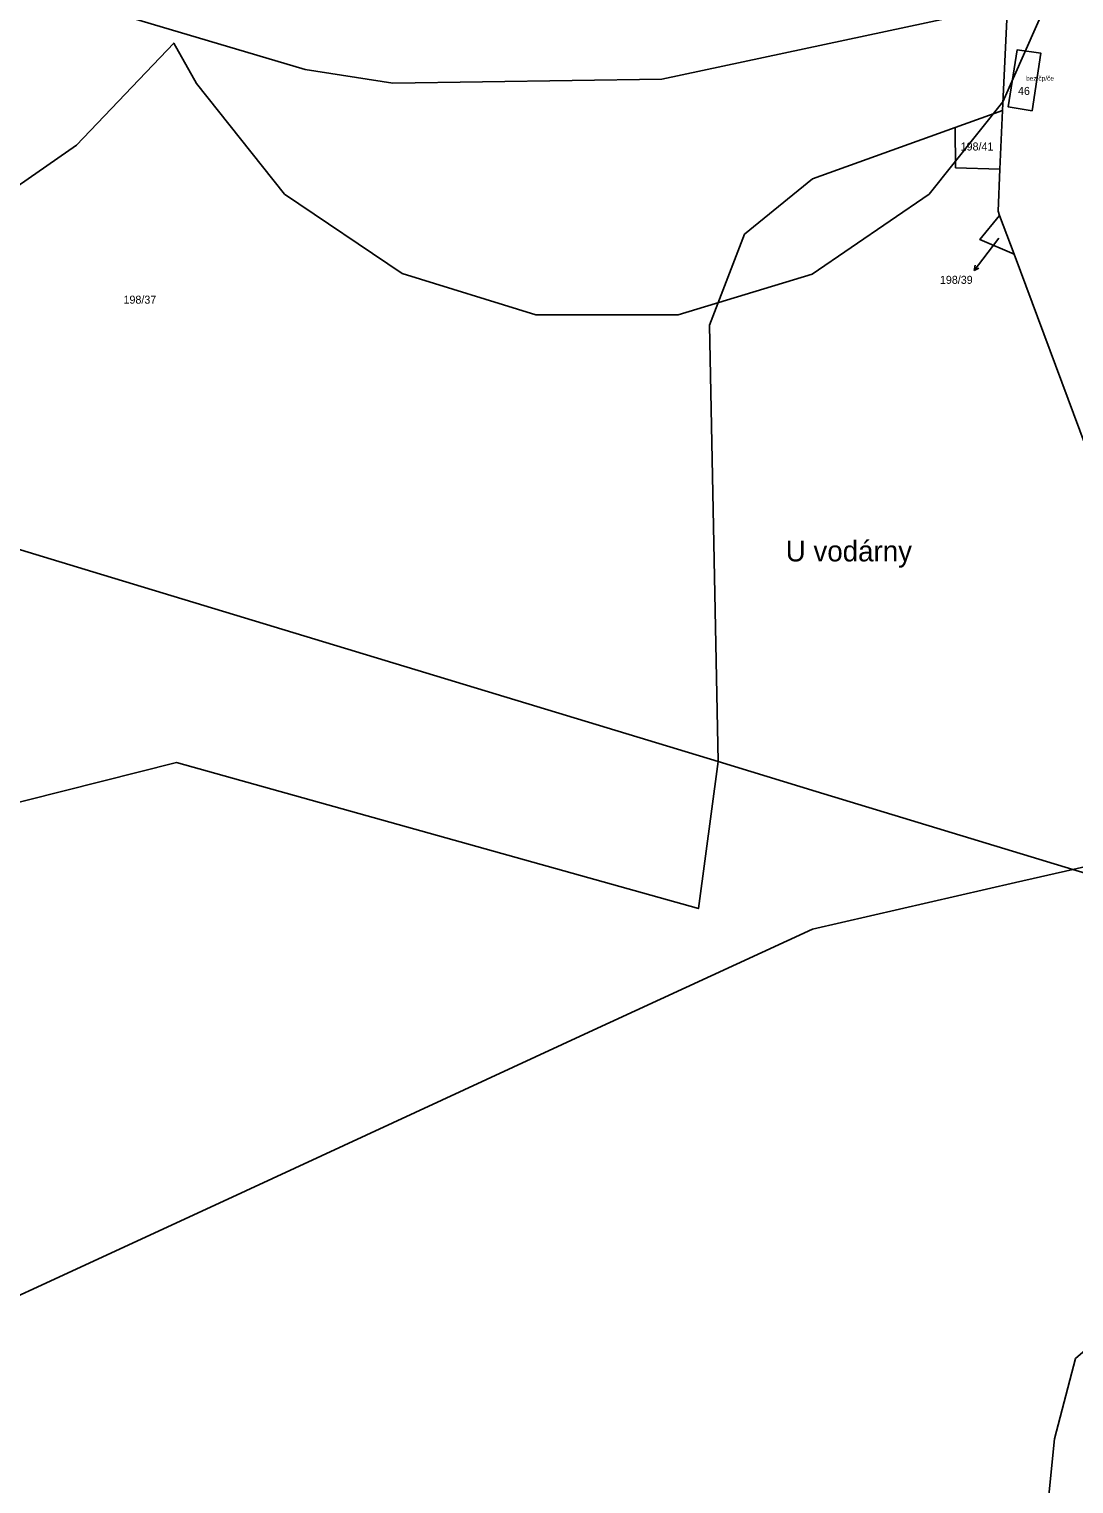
# Model space of a CAD drawing. Extents: x -882150 to -879379, y -1022570 to -1019819.
# Drawn here: x -880484.4 to -880262.5, y -1020448.8 to -1020139.9 of the extents above; entities that cross this region are included whole.
import ezdxf

# ---------------------------------------------------------------- set-up
doc = ezdxf.new("R2010")
doc.units = 0
for name, color, linetype in [('Definiční body', 7, 'Continuous'), ('Hranice parcel', 7, 'Continuous'), ('Parcelní čísla', 7, 'Continuous'), ('Polygon budovy', 7, 'Continuous'), ('Pop  PČ popisy', 7, 'Continuous'), ('Vnitřní kresba', 7, 'Continuous')]:
    doc.layers.add(name, color=color, linetype=linetype)

msp = doc.modelspace()

# ---------------------------------------------------------------- linework, layer by layer
at = {"layer": 'Hranice parcel'}
for p, q in [((-880276.63, -1020134.84), (-880277.64, -1020157.16)), ((-880277.64, -1020157.16), (-880287.69, -1020160.77)), ((-880278.21, -1020169.62), (-880277.64, -1020157.16)), ((-880275.21, -1020187.64), (-880278.26, -1020179.47)), ((-880262.73, -1020318.32), (-880184.91, -1020341.96))]:
    msp.add_line(p, q, dxfattribs=at)
for points in [[(-880502.38, -1020102.49), (-880497.06, -1020107.99), (-880478.95, -1020132.59), (-880425.73, -1020148.42), (-880407.16, -1020151.31), (-880349.97, -1020150.48), (-880276.63, -1020134.84)], [(-880269.51, -1020144.98), (-880274.57, -1020144.27), (-880276.42, -1020156.38), (-880271.37, -1020157.21), (-880269.51, -1020144.98)], [(-880287.69, -1020160.77), (-880318.03, -1020171.68), (-880332.46, -1020183.44), (-880339.85, -1020202.75), (-880338.05, -1020295.44)], [(-880287.69, -1020160.77), (-880287.61, -1020169.31), (-880278.21, -1020169.62)], [(-880278.21, -1020169.62), (-880278.61, -1020178.52), (-880278.26, -1020179.47)], [(-880278.26, -1020179.47), (-880282.45, -1020184.57), (-880275.21, -1020187.64)], [(-880275.21, -1020187.64), (-880258.76, -1020231.77), (-880145.16, -1020240.12)], [(-880617.77, -1020210.48), (-880622.75, -1020237.87), (-880508.97, -1020309.69), (-880453.04, -1020295.61), (-880342.22, -1020326.65), (-880338.05, -1020295.44)], [(-880338.05, -1020295.44), (-880470.83, -1020255.11), (-880617.77, -1020210.48)], [(-880262.73, -1020318.32), (-880317.23, -1020301.77), (-880338.05, -1020295.44)], [(-880184.91, -1020341.96), (-880161, -1020295), (-880262.73, -1020318.32)], [(-880682, -1020499), (-880673.83, -1020495.23), (-880595.38, -1020459.02), (-880526.65, -1020427.3), (-880443.12, -1020388.75), (-880366.39, -1020353.34), (-880317.99, -1020331), (-880274.92, -1020321.12), (-880262.73, -1020318.32)], [(-880224.37, -1020419.46), (-880231.68, -1020412.27), (-880243.47, -1020406.04), (-880262.13, -1020422.22), (-880266.61, -1020439.29), (-880273.4, -1020507.16), (-880285.17, -1020537.62), (-880295.63, -1020564.31)]]:
    msp.add_lwpolyline(points, dxfattribs=at)
at = {"layer": 'Polygon budovy'}
msp.add_lwpolyline([(-880274.57, -1020144.27), (-880276.42, -1020156.38), (-880271.37, -1020157.21), (-880269.51, -1020144.98)], close=True, dxfattribs=at)
at = {"layer": 'Pop  PČ popisy'}
for p, q in [((-880278.46, -1020184.29), (-880281.85, -1020188.73)), ((-880281.85, -1020188.73), (-880283.656, -1020191.127)), ((-880283.656, -1020191.127), (-880283.453, -1020190.026)), ((-880283.656, -1020191.127), (-880282.653, -1020190.628))]:
    msp.add_line(p, q, dxfattribs=at)
at = {"layer": 'Vnitřní kresba'}
for points in [[(-880293.2, -1020174.89), (-880277.57, -1020155.32), (-880263.6, -1020123.56)], [(-880615.29, -1020193.51), (-880585.87, -1020199.54), (-880556.01, -1020199.53), (-880526.59, -1020193.5), (-880498.86, -1020181.6), (-880474.31, -1020164.53), (-880453.64, -1020142.82), (-880448.85, -1020151.39), (-880430.15, -1020174.89), (-880405.16, -1020191.79), (-880376.74, -1020200.57), (-880346.52, -1020200.57), (-880318.05, -1020191.93), (-880293.2, -1020174.89)]]:
    msp.add_lwpolyline(points, dxfattribs=at)

# ---------------------------------------------------------------- texts
at = {"layer": 'Definiční body'}
msp.add_text('bez čp/če', height=1, dxfattribs=at).set_placement((-880272.64, -1020150.82))
at = {"layer": 'Parcelní čísla'}
for s, p in [('46', (-880274.37, -1020153.84)), ('198/41', (-880286.546, -1020165.64)), ('198/39', (-880290.945, -1020193.958)), ('198/37', (-880464.32, -1020198.17))]:
    msp.add_text(s, height=1.7, dxfattribs=at).set_placement(p)
at = {"layer": 'Pop  PČ popisy'}
msp.add_text('U vodárny', height=4.4, dxfattribs=at).set_placement((-880323.69, -1020252.91))

doc.saveas('drawing.dxf')
